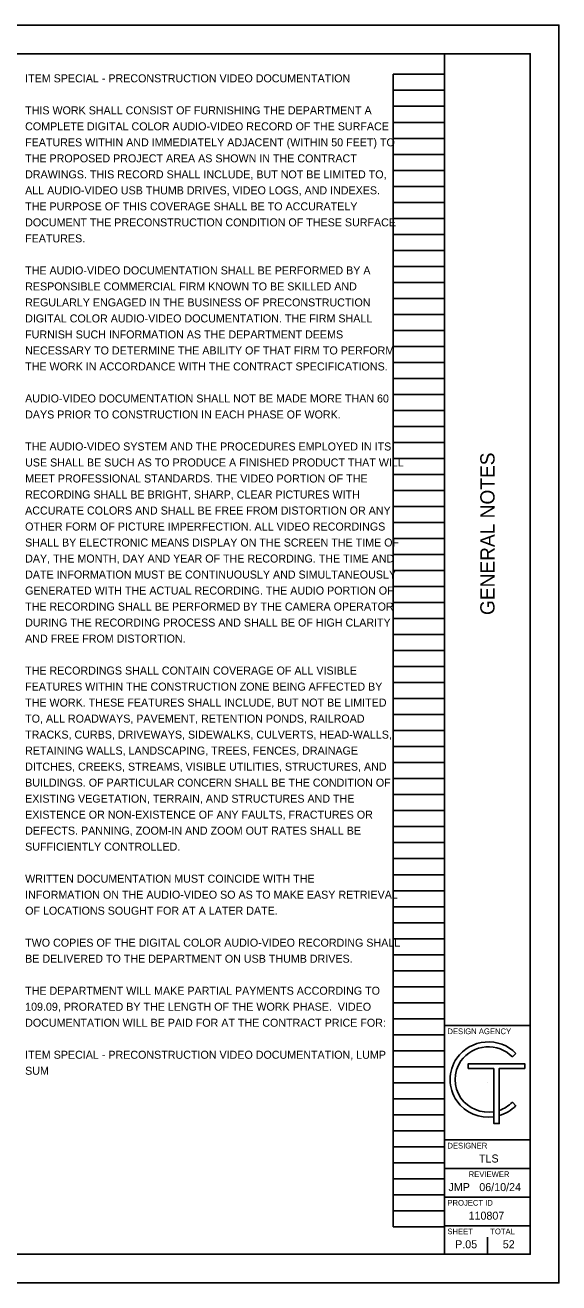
# Model space of a CAD drawing. Extents: x -8.9 to 34, y 0 to 22.
# Drawn here: x 24.66 to 34, y 0 to 22 of the extents above; entities that cross this region are included whole.
import ezdxf

# ---------------------------------------------------------------- set-up
doc = ezdxf.new("R2010")
doc.units = 0
for name, color, linetype in [('Default', 7, 'Continuous'), ('SH_Border', 7, 'Continuous'), ('SH_Cut_Line', 7, 'Continuous'), ('SH_Data', 7, 'Continuous'), ('SH_Text', 7, 'Continuous')]:
    doc.layers.add(name, color=color, linetype=linetype)

msp = doc.modelspace()

# ---------------------------------------------------------------- linework, layer by layer
at = {"layer": 'SH_Border'}
for p, q in [((32, 0.5), (32, 21.5)), ((32, 4.5), (33.5, 4.5)), ((32, 2.5), (33.5, 2.5)), ((32, 2), (33.5, 2)), ((32, 1.5), (33.5, 1.5)), ((32, 1), (33.5, 1))]:
    msp.add_line(p, q, dxfattribs=at)
msp.add_lwpolyline([(1.5, 21.5), (33.5, 21.5), (33.5, 0.5), (1.5, 0.5)], close=True, dxfattribs=at)
at = {"layer": 'SH_Cut_Line'}
msp.add_lwpolyline([(0, 0), (34, 0), (34, 22), (0, 22)], close=True, dxfattribs=at)
at = {"layer": 'SH_Data'}
for p, q in [((31.1, 0.98), (31.1, 21.14)), ((31.1, 21.14), (32, 21.14)), ((32, 0.98), (32, 21.14)), ((31.1, 20.86), (32, 20.86)), ((31.1, 20.58), (32, 20.58)), ((31.1, 20.3), (32, 20.3)), ((31.1, 20.02), (32, 20.02)), ((31.1, 19.74), (32, 19.74)), ((31.1, 19.46), (32, 19.46)), ((31.1, 19.18), (32, 19.18)), ((31.1, 18.9), (32, 18.9)), ((31.1, 18.62), (32, 18.62)), ((31.1, 18.34), (32, 18.34)), ((31.1, 18.06), (32, 18.06)), ((31.1, 17.78), (32, 17.78)), ((31.1, 17.5), (32, 17.5)), ((31.1, 17.22), (32, 17.22)), ((31.1, 16.94), (32, 16.94)), ((31.1, 16.66), (32, 16.66)), ((31.1, 16.38), (32, 16.38)), ((31.1, 16.1), (32, 16.1)), ((31.1, 15.82), (32, 15.82)), ((31.1, 15.54), (32, 15.54)), ((31.1, 15.26), (32, 15.26)), ((31.1, 14.98), (32, 14.98)), ((31.1, 14.7), (32, 14.7)), ((31.1, 14.42), (32, 14.42)), ((31.1, 14.14), (32, 14.14)), ((31.1, 13.86), (32, 13.86)), ((31.1, 13.58), (32, 13.58)), ((31.1, 13.3), (32, 13.3)), ((31.1, 13.02), (32, 13.02)), ((31.1, 12.74), (32, 12.74)), ((31.1, 12.46), (32, 12.46)), ((31.1, 12.18), (32, 12.18)), ((31.1, 11.9), (32, 11.9)), ((31.1, 11.62), (32, 11.62)), ((31.1, 11.34), (32, 11.34)), ((31.1, 11.06), (32, 11.06)), ((31.1, 10.78), (32, 10.78)), ((31.1, 10.5), (32, 10.5)), ((31.1, 10.22), (32, 10.22)), ((31.1, 9.94), (32, 9.94)), ((31.1, 9.66), (32, 9.66)), ((31.1, 9.38), (32, 9.38)), ((31.1, 9.1), (32, 9.1)), ((31.1, 8.82), (32, 8.82)), ((31.1, 8.54), (32, 8.54)), ((31.1, 8.26), (32, 8.26)), ((31.1, 7.98), (32, 7.98)), ((31.1, 7.7), (32, 7.7)), ((31.1, 7.42), (32, 7.42)), ((31.1, 7.14), (32, 7.14)), ((31.1, 6.86), (32, 6.86)), ((31.1, 6.58), (32, 6.58)), ((31.1, 6.3), (32, 6.3)), ((31.1, 6.02), (32, 6.02)), ((31.1, 5.74), (32, 5.74)), ((31.1, 5.46), (32, 5.46)), ((31.1, 5.18), (32, 5.18)), ((31.1, 4.9), (32, 4.9)), ((31.1, 4.62), (32, 4.62)), ((31.1, 4.34), (32, 4.34)), ((31.1, 4.06), (32, 4.06)), ((31.1, 3.78), (32, 3.78)), ((31.1, 3.5), (32, 3.5)), ((32.75, 3.5), (32.75, 3.5)), ((31.1, 3.22), (32, 3.22)), ((31.1, 2.94), (32, 2.94)), ((31.1, 2.66), (32, 2.66)), ((31.1, 2.38), (32, 2.38)), ((31.1, 2.1), (32, 2.1)), ((31.1, 1.82), (32, 1.82)), ((31.1, 1.54), (32, 1.54)), ((31.1, 1.26), (32, 1.26)), ((31.1, 0.98), (32, 0.98)), ((32.375, 0.675), (32.375, 0.675)), ((32.75, 0.5), (32.75, 0.8))]:
    msp.add_line(p, q, dxfattribs=at)
at = {"layer": 'SH_Text'}
for p, q in [((33.249, 4.013), (33.187, 3.952)), ((33.249, 4.013), (33.187, 3.952)), ((33.402, 3.833), (32.414, 3.833)), ((32.414, 3.833), (32.414, 3.751)), ((32.414, 3.751), (32.863, 3.751)), ((32.863, 3.751), (32.863, 2.785)), ((32.956, 2.785), (32.956, 3.751)), ((32.956, 3.751), (33.402, 3.751)), ((33.402, 3.751), (33.402, 3.833)), ((33.187, 3.16), (33.249, 3.099)), ((33.187, 3.16), (33.249, 3.099)), ((32.863, 2.993), (32.863, 2.905)), ((32.863, 2.993), (32.863, 2.905)), ((32.956, 2.925), (32.956, 3.016)), ((32.956, 2.925), (32.956, 3.016)), ((32.863, 2.785), (32.956, 2.785))]:
    msp.add_line(p, q, dxfattribs=at)
msp.add_lwpolyline([(32.863, 3.751), (32.863, 2.785), (32.956, 2.785), (32.956, 3.751), (33.402, 3.751), (33.402, 3.833), (32.414, 3.833), (32.414, 3.751)], close=True, dxfattribs=at)
for centre, radius, start, end in [((32.766, 3.535), 0.68, 44.7027, 144.3276), ((32.766, 3.535), 0.68, 44.7027, 144.3276), ((32.766, 3.535), 0.593, 44.7362, 144.1102), ((32.766, 3.535), 0.593, 44.7362, 144.1102), ((32.764, 3.556), 0.666, 145.7329, 214.2671), ((32.764, 3.556), 0.666, 145.7329, 214.2671), ((32.764, 3.556), 0.579, 145.7266, 214.2734), ((32.764, 3.556), 0.579, 145.7266, 214.2734), ((32.766, 3.578), 0.68, 215.6724, 278.2613), ((32.766, 3.578), 0.68, 215.6724, 278.2613), ((32.766, 3.578), 0.593, 215.8898, 279.4882), ((32.766, 3.578), 0.593, 215.8898, 279.4882), ((32.766, 3.578), 0.593, 288.6992, 315.2638), ((32.766, 3.578), 0.593, 288.6992, 315.2638), ((32.766, 3.578), 0.68, 286.2291, 315.2973), ((32.766, 3.578), 0.68, 286.2291, 315.2973)]:
    msp.add_arc(centre, radius, start, end, dxfattribs=at)

# ---------------------------------------------------------------- texts
at = {"layer": 'Default'}
for s, p in [('ITEM SPECIAL - PRECONSTRUCTION VIDEO DOCUMENTATION', (24.66, 21)), ('THIS WORK SHALL CONSIST OF FURNISHING THE DEPARTMENT A ', (24.66, 20.44)), ('COMPLETE DIGITAL COLOR AUDIO-VIDEO RECORD OF THE SURFACE ', (24.66, 20.16)), ('FEATURES WITHIN AND IMMEDIATELY ADJACENT (WITHIN 50 FEET) TO ', (24.66, 19.88)), ('THE PROPOSED PROJECT AREA AS SHOWN IN THE CONTRACT ', (24.66, 19.6)), ('DRAWINGS. THIS RECORD SHALL INCLUDE, BUT NOT BE LIMITED TO, ', (24.66, 19.32)), ('ALL AUDIO-VIDEO USB THUMB DRIVES, VIDEO LOGS, AND INDEXES.  ', (24.66, 19.04)), ('THE PURPOSE OF THIS COVERAGE SHALL BE TO ACCURATELY ', (24.66, 18.76)), ('DOCUMENT THE PRECONSTRUCTION CONDITION OF THESE SURFACE ', (24.66, 18.48)), ('FEATURES.', (24.66, 18.2)), ('THE AUDIO-VIDEO DOCUMENTATION SHALL BE PERFORMED BY A ', (24.66, 17.64)), ('RESPONSIBLE COMMERCIAL FIRM KNOWN TO BE SKILLED AND ', (24.66, 17.36)), ('REGULARLY ENGAGED IN THE BUSINESS OF PRECONSTRUCTION ', (24.66, 17.08)), ('DIGITAL COLOR AUDIO-VIDEO DOCUMENTATION. THE FIRM SHALL ', (24.66, 16.8)), ('FURNISH SUCH INFORMATION AS THE DEPARTMENT DEEMS ', (24.66, 16.52)), ('NECESSARY TO DETERMINE THE ABILITY OF THAT FIRM TO PERFORM ', (24.66, 16.24)), ('THE WORK IN ACCORDANCE WITH THE CONTRACT SPECIFICATIONS.', (24.66, 15.96)), ('AUDIO-VIDEO DOCUMENTATION SHALL NOT BE MADE MORE THAN 60 ', (24.66, 15.4)), ('DAYS PRIOR TO CONSTRUCTION IN EACH PHASE OF WORK.', (24.66, 15.12)), ('THE AUDIO-VIDEO SYSTEM AND THE PROCEDURES EMPLOYED IN ITS ', (24.66, 14.56)), ('USE SHALL BE SUCH AS TO PRODUCE A FINISHED PRODUCT THAT WILL ', (24.66, 14.28)), ('MEET PROFESSIONAL STANDARDS. THE VIDEO PORTION OF THE ', (24.66, 14)), ('RECORDING SHALL BE BRIGHT, SHARP, CLEAR PICTURES WITH ', (24.66, 13.72)), ('ACCURATE COLORS AND SHALL BE FREE FROM DISTORTION OR ANY ', (24.66, 13.44)), ('OTHER FORM OF PICTURE IMPERFECTION. ALL VIDEO RECORDINGS ', (24.66, 13.16)), ('SHALL BY ELECTRONIC MEANS DISPLAY ON THE SCREEN THE TIME OF ', (24.66, 12.88)), ('DAY, THE MONTH, DAY AND YEAR OF THE RECORDING. THE TIME AND ', (24.66, 12.6)), ('DATE INFORMATION MUST BE CONTINUOUSLY AND SIMULTANEOUSLY ', (24.66, 12.32)), ('GENERATED WITH THE ACTUAL RECORDING. THE AUDIO PORTION OF ', (24.66, 12.04)), ('THE RECORDING SHALL BE PERFORMED BY THE CAMERA OPERATOR ', (24.66, 11.76)), ('DURING THE RECORDING PROCESS AND SHALL BE OF HIGH CLARITY ', (24.66, 11.48)), ('AND FREE FROM DISTORTION.', (24.66, 11.2)), ('THE RECORDINGS SHALL CONTAIN COVERAGE OF ALL VISIBLE ', (24.66, 10.64)), ('FEATURES WITHIN THE CONSTRUCTION ZONE BEING AFFECTED BY ', (24.66, 10.36)), ('THE WORK. THESE FEATURES SHALL INCLUDE, BUT NOT BE LIMITED ', (24.66, 10.08)), ('TO, ALL ROADWAYS, PAVEMENT, RETENTION PONDS, RAILROAD ', (24.66, 9.8)), ('TRACKS, CURBS, DRIVEWAYS, SIDEWALKS, CULVERTS, HEAD-WALLS, ', (24.66, 9.52)), ('RETAINING WALLS, LANDSCAPING, TREES, FENCES, DRAINAGE ', (24.66, 9.24)), ('DITCHES, CREEKS, STREAMS, VISIBLE UTILITIES, STRUCTURES, AND ', (24.66, 8.96)), ('BUILDINGS. OF PARTICULAR CONCERN SHALL BE THE CONDITION OF ', (24.66, 8.68)), ('EXISTING VEGETATION, TERRAIN, AND STRUCTURES AND THE ', (24.66, 8.4)), ('EXISTENCE OR NON-EXISTENCE OF ANY FAULTS, FRACTURES OR ', (24.66, 8.12)), ('DEFECTS. PANNING, ZOOM-IN AND ZOOM OUT RATES SHALL BE ', (24.66, 7.84)), ('SUFFICIENTLY CONTROLLED.', (24.66, 7.56)), ('WRITTEN DOCUMENTATION MUST COINCIDE WITH THE ', (24.66, 7)), ('INFORMATION ON THE AUDIO-VIDEO SO AS TO MAKE EASY RETRIEVAL ', (24.66, 6.72)), ('OF LOCATIONS SOUGHT FOR AT A LATER DATE.', (24.66, 6.44)), ('TWO COPIES OF THE DIGITAL COLOR AUDIO-VIDEO RECORDING SHALL ', (24.66, 5.88)), ('BE DELIVERED TO THE DEPARTMENT ON USB THUMB DRIVES.', (24.66, 5.6)), ('THE DEPARTMENT WILL MAKE PARTIAL PAYMENTS ACCORDING TO ', (24.66, 5.04)), ('109.09, PRORATED BY THE LENGTH OF THE WORK PHASE.  VIDEO ', (24.66, 4.76)), ('DOCUMENTATION WILL BE PAID FOR AT THE CONTRACT PRICE FOR:', (24.66, 4.48)), ('ITEM SPECIAL - PRECONSTRUCTION VIDEO DOCUMENTATION, LUMP ', (24.66, 3.92)), ('SUM', (24.66, 3.64))]:
    msp.add_text(s, height=0.14, dxfattribs=at).set_placement(p)
at = {"layer": 'SH_Data'}
msp.add_text('GENERAL NOTES', height=0.25, rotation=90, dxfattribs=at).set_placement((32.875, 11.682))
for s, height, p in [('DESIGN AGENCY', 0.1, (32.05, 4.35)), ('DESIGNER', 0.1, (32.05, 2.35)), ('TLS', 0.14, (32.603, 2.105)), ('REVIEWER', 0.1, (32.422, 1.85)), ('JMP', 0.14, (32.068, 1.605)), ('06/10/24', 0.14, (32.608, 1.605)), ('PROJECT ID', 0.1, (32.05, 1.35)), ('110807', 0.14, (32.42, 1.105)), ('SHEET', 0.1, (32.05, 0.85)), ('TOTAL', 0.1, (32.8, 0.85)), ('P.05', 0.14, (32.185, 0.605)), ('52', 0.14, (33.019, 0.605))]:
    msp.add_text(s, height=height, dxfattribs=at).set_placement(p)

doc.saveas('drawing.dxf')
